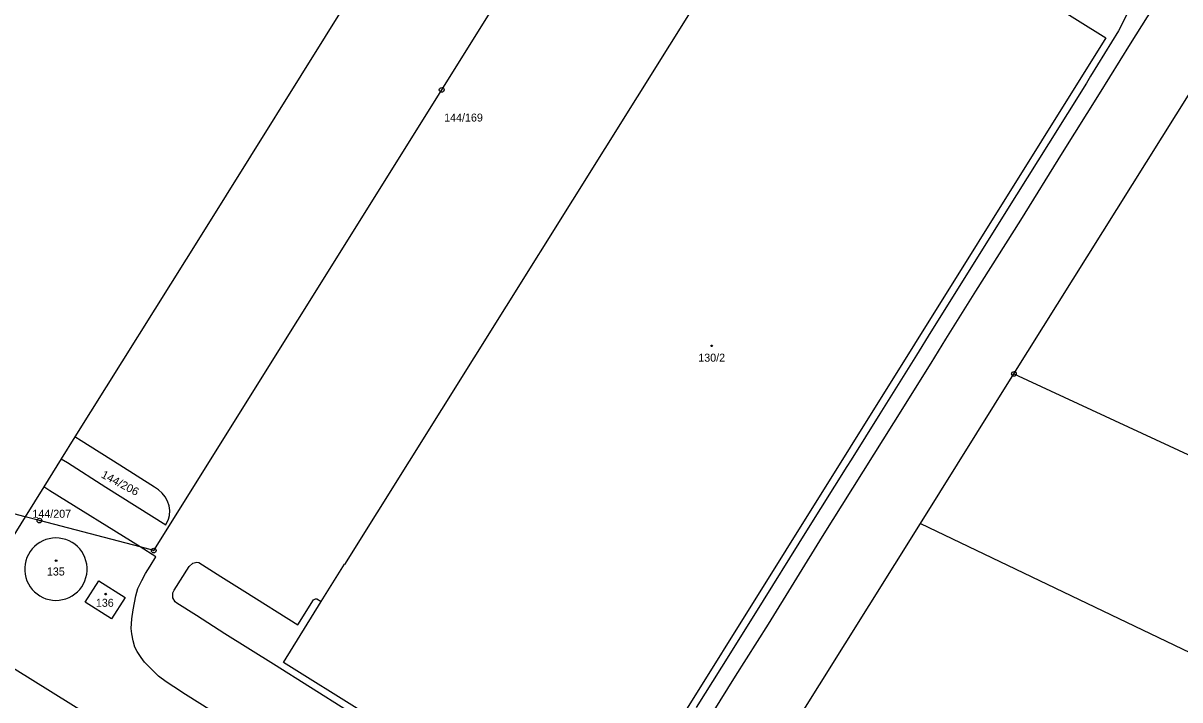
# Model space of a CAD drawing. Extents: x -645290 to -643454, y -1064771 to -1062356.
# Drawn here: x -644318.9 to -644073.2, y -1063369.7 to -1063226 of the extents above; entities that cross this region are included whole.
import ezdxf
from ezdxf.enums import TextEntityAlignment as Align

# ---------------------------------------------------------------- set-up
doc = ezdxf.new("R2010")
doc.units = 0
doc.header["$LTSCALE"] = 0.68
for name, color, linetype, lineweight in [('1', 7, 'Continuous', 25), ('5', 7, 'Continuous', 25), ('8', 7, 'Continuous', 25)]:
    doc.layers.add(name, color=color, linetype=linetype, lineweight=lineweight)
doc.layers.add('2', color=7, linetype='Continuous')

msp = doc.modelspace()

# ---------------------------------------------------------------- linework, layer by layer
at = {"layer": '1'}
for p, q in [((-644224.67, -1063180.78), (-644280.94, -1063270.85)), ((-644080.77, -1063216.97), (-644086.24, -1063227.71)), ((-644077.74, -1063220.84), (-644083.77, -1063230.42)), ((-644086.24, -1063227.71), (-644092.19, -1063237.34)), ((-644108.45, -1063300.52), (-644064.43, -1063230.22)), ((-644083.77, -1063230.42), (-644090.33, -1063241.04)), ((-644093.06, -1063238.8), (-644101.13, -1063251.7)), ((-644092.19, -1063237.34), (-644093.06, -1063238.8)), ((-644090.33, -1063241.04), (-644098.22, -1063253.57)), ((-644101.13, -1063251.7), (-644110.15, -1063266.1)), ((-644098.22, -1063253.57), (-644107.05, -1063267.85)), ((-644110.15, -1063266.1), (-644119.6, -1063281.15)), ((-644107.05, -1063267.85), (-644116.63, -1063282.98)), ((-644280.94, -1063270.85), (-644307.86, -1063313.88)), ((-644119.6, -1063281.15), (-644126.07, -1063291.59)), ((-644116.63, -1063282.98), (-644122.97, -1063293.16)), ((-644126.07, -1063291.59), (-644129.12, -1063296.51)), ((-644122.97, -1063293.16), (-644126.11, -1063298.2)), ((-644129.12, -1063296.51), (-644136.95, -1063309.01)), ((-644126.11, -1063298.2), (-644134, -1063310.86)), ((-644128.32, -1063332.26), (-644108.45, -1063300.52)), ((-644108.45, -1063300.52), (-644032.62, -1063335.66)), ((-644136.95, -1063309.01), (-644143.04, -1063318.78)), ((-644405.68, -1063310.31), (-644297.96, -1063377.21)), ((-644134, -1063310.86), (-644149.21, -1063335.03)), ((-644307.86, -1063313.88), (-644310.77, -1063318.53)), ((-644306.58, -1063314.69), (-644307.86, -1063313.88)), ((-644298.31, -1063319.88), (-644306.58, -1063314.69)), ((-644310.77, -1063318.53), (-644314.5, -1063324.5)), ((-644310.77, -1063318.53), (-644309.47, -1063319.34)), ((-644309.47, -1063319.34), (-644301.32, -1063324.57)), ((-644290.97, -1063324.55), (-644298.31, -1063319.88)), ((-644143.04, -1063318.78), (-644143.93, -1063320.16)), ((-644318.46, -1063330.83), (-644352.62, -1063321.85)), ((-644143.93, -1063320.16), (-644152.15, -1063333.27)), ((-644314.5, -1063324.5), (-644318.46, -1063330.83)), ((-644313.23, -1063325.36), (-644314.5, -1063324.5)), ((-644301.32, -1063324.57), (-644288.56, -1063332.54)), ((-644290.09, -1063325.12), (-644290.97, -1063324.55)), ((-644294.03, -1063337.25), (-644313.23, -1063325.36)), ((-644289.34, -1063325.83), (-644290.09, -1063325.12)), ((-644288.7, -1063326.59), (-644289.34, -1063325.83)), ((-644288.18, -1063327.5), (-644288.7, -1063326.59)), ((-644287.89, -1063328.5), (-644288.18, -1063327.5)), ((-644287.74, -1063329.51), (-644287.89, -1063328.5)), ((-644287.82, -1063330.54), (-644287.74, -1063329.51)), ((-644318.46, -1063330.83), (-644324.02, -1063339.73)), ((-644315.42, -1063331.63), (-644318.46, -1063330.83)), ((-644294.03, -1063337.25), (-644315.42, -1063331.63)), ((-644288.56, -1063332.54), (-644287.98, -1063331.36)), ((-644287.98, -1063331.36), (-644287.82, -1063330.54)), ((-644152.15, -1063333.27), (-644163.68, -1063351.81)), ((-644157, -1063378.05), (-644128.32, -1063332.26)), ((-644128.32, -1063332.26), (-644060.42, -1063364.75)), ((-644149.21, -1063335.03), (-644160.65, -1063353.62)), ((-644290.66, -1063339.34), (-644294.03, -1063337.25)), ((-644291.14, -1063338.01), (-644294.03, -1063337.25)), ((-644291.91, -1063341.35), (-644290.66, -1063339.34)), ((-644292.87, -1063342.9), (-644291.91, -1063341.35)), ((-644286.82, -1063346.45), (-644283.62, -1063341.4)), ((-644283.62, -1063341.4), (-644282.85, -1063340.7)), ((-644282.85, -1063340.7), (-644281.95, -1063340.49)), ((-644281.95, -1063340.49), (-644281.57, -1063340.55)), ((-644281.57, -1063340.55), (-644276.88, -1063343.5)), ((-644305.7, -1063348.99), (-644302.81, -1063344.43)), ((-644302.81, -1063344.43), (-644297.18, -1063347.94)), ((-644294.52, -1063346.05), (-644293.69, -1063344.36)), ((-644293.69, -1063344.36), (-644292.87, -1063342.9)), ((-644276.88, -1063343.5), (-644271.79, -1063346.69)), ((-644294.96, -1063347.61), (-644294.52, -1063346.05)), ((-644287.11, -1063346.99), (-644286.82, -1063346.45)), ((-644271.79, -1063346.69), (-644260.5, -1063353.79)), ((-644300.07, -1063352.53), (-644305.7, -1063348.99)), ((-644297.18, -1063347.94), (-644300.07, -1063352.53)), ((-644295.53, -1063350.58), (-644294.96, -1063347.61)), ((-644287.09, -1063348.03), (-644287.11, -1063346.99)), ((-644286.57, -1063348.87), (-644287.09, -1063348.03)), ((-644286.21, -1063349.21), (-644286.57, -1063348.87)), ((-644282.08, -1063351.82), (-644286.21, -1063349.21)), ((-644260.5, -1063353.79), (-644257.19, -1063348.46)), ((-644257.19, -1063348.46), (-644256.77, -1063348.24)), ((-644256.77, -1063348.24), (-644256.53, -1063348.27)), ((-644256.53, -1063348.27), (-644255.56, -1063348.85)), ((-644295.78, -1063352.47), (-644295.53, -1063350.58)), ((-644276.02, -1063355.65), (-644282.08, -1063351.82)), ((-644163.68, -1063351.81), (-644170.57, -1063362.75)), ((-644295.9, -1063354.56), (-644295.78, -1063352.47)), ((-644160.65, -1063353.62), (-644167.65, -1063364.69)), ((-644295.77, -1063355.72), (-644295.9, -1063354.56)), ((-644295.52, -1063357.16), (-644295.77, -1063355.72)), ((-644265.68, -1063362.14), (-644276.02, -1063355.65)), ((-644295.17, -1063358.52), (-644295.52, -1063357.16)), ((-644294.68, -1063359.47), (-644295.17, -1063358.52)), ((-644293.82, -1063360.7), (-644294.68, -1063359.47)), ((-644293.06, -1063361.67), (-644293.82, -1063360.7)), ((-644292.2, -1063362.63), (-644293.06, -1063361.67)), ((-644291.13, -1063363.67), (-644292.2, -1063362.63)), ((-644290.11, -1063364.66), (-644291.13, -1063363.67)), ((-644250, -1063372.02), (-644265.68, -1063362.14)), ((-644170.57, -1063362.75), (-644175.9, -1063371.34)), ((-644288.52, -1063365.86), (-644290.11, -1063364.66)), ((-644286.84, -1063366.94), (-644288.52, -1063365.86)), ((-644167.65, -1063364.69), (-644172.52, -1063372.53)), ((-644284.36, -1063368.55), (-644286.84, -1063366.94)), ((-644278.9, -1063372.05), (-644284.36, -1063368.55))]:
    msp.add_line(p, q, dxfattribs=at)
for points in [[(-644162.87, -1063200.63), (-644154.86, -1063187.84), (-644138.14, -1063198.3), (-644138.19, -1063198.38), (-644088.93, -1063229.19), (-644197.53, -1063402.92), (-644246.76, -1063372.17), (-644246.82, -1063372.26), (-644263.58, -1063361.75), (-644255.56, -1063348.85)], [(-644291.14, -1063338.01), (-644229.98, -1063240.22), (-644200.35, -1063192.82)], [(-644255.56, -1063348.85), (-644250.61, -1063340.89), (-644250.52, -1063340.95), (-644167.81, -1063208.72), (-644167.9, -1063208.67), (-644162.87, -1063200.63)]]:
    msp.add_lwpolyline(points, dxfattribs=at)
msp.add_lwpolyline([(-644311.905, -1063348.579), (-644311.189, -1063348.54), (-644310.482, -1063348.424), (-644309.791, -1063348.232), (-644309.125, -1063347.967), (-644308.491, -1063347.631), (-644307.897, -1063347.229), (-644307.351, -1063346.764), (-644306.858, -1063346.244), (-644306.424, -1063345.673), (-644306.054, -1063345.058), (-644305.753, -1063344.408), (-644305.524, -1063343.728), (-644305.37, -1063343.028), (-644305.292, -1063342.315), (-644305.292, -1063341.598), (-644305.37, -1063340.885), (-644305.524, -1063340.184), (-644305.753, -1063339.505), (-644306.054, -1063338.854), (-644306.424, -1063338.24), (-644306.858, -1063337.669), (-644307.351, -1063337.148), (-644307.897, -1063336.684), (-644308.491, -1063336.281), (-644309.125, -1063335.945), (-644309.791, -1063335.68), (-644310.482, -1063335.488), (-644311.189, -1063335.372), (-644311.905, -1063335.333), (-644312.622, -1063335.372), (-644313.329, -1063335.488), (-644314.02, -1063335.68), (-644314.686, -1063335.945), (-644315.32, -1063336.281), (-644315.914, -1063336.684), (-644316.46, -1063337.148), (-644316.953, -1063337.669), (-644317.387, -1063338.24), (-644317.757, -1063338.854), (-644318.058, -1063339.505), (-644318.287, -1063340.184), (-644318.441, -1063340.885), (-644318.519, -1063341.598), (-644318.519, -1063342.315), (-644318.441, -1063343.028), (-644318.287, -1063343.728), (-644318.058, -1063344.408), (-644317.757, -1063345.058), (-644317.387, -1063345.673), (-644316.953, -1063346.244), (-644316.46, -1063346.764), (-644315.914, -1063347.229), (-644315.32, -1063347.631), (-644314.686, -1063347.967), (-644314.02, -1063348.232), (-644313.329, -1063348.424), (-644312.622, -1063348.54)], close=True, dxfattribs=at)
at = {"layer": '5'}
for centre in [(-644172.6568, -1063294.5492), (-644311.8668, -1063340.1692), (-644301.3268, -1063347.2492)]:
    msp.add_circle(centre, 0.175, dxfattribs=at)
at = {"layer": '8'}
for centre, radius in [((-644229.98, -1063240.2199), 0.5), ((-644229.98, -1063240.2199), 0.0303), ((-644108.45, -1063300.5199), 0.5), ((-644108.45, -1063300.5199), 0.0303), ((-644315.42, -1063331.6299), 0.5), ((-644315.42, -1063331.6299), 0.0303), ((-644291.14, -1063338.0099), 0.5), ((-644291.14, -1063338.0099), 0.0303)]:
    msp.add_circle(centre, radius, dxfattribs=at)

# ---------------------------------------------------------------- texts
at = {"layer": '2'}
for s, p in [('144/169', (-644225.349, -1063246.945)), ('130/2', (-644172.64, -1063297.915)), ('144/207', (-644312.789, -1063331.045)), ('135', (-644311.929, -1063343.304)), ('136', (-644301.529, -1063349.945))]:
    msp.add_text(s, height=1.7, dxfattribs=at).set_placement(p, align=Align.CENTER)
at = {"layer": '2', "width": 1.05}
msp.add_text('144/206', height=1.7, rotation=332, dxfattribs=at).set_placement((-644302.459, -1063322.405))

doc.saveas('drawing.dxf')
